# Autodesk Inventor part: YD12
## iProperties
baan no: 0
Author: kevin.guzniczak
Shininess: 60.0
PropertySet Name: _Private Model Information
Created: 2000-12
Part Number: YD12
Material: Steel, Mild
Document SubType Name: Modeling
Designer: kevin.guzniczak
Description: SPUR GEAR
Vendor: BOSTON
Control State: 0
Master: False
Checked Out: False
PropertySet Name: Design Tracking Control
Density: 0.0
Volumn: 0.0
Area: 0.0
PropertySet Name: Model Information
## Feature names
1. Extrusion2
2. Extrusion4
3. Circular Pattern1
4. Extrusion5
5. Extrusion6
